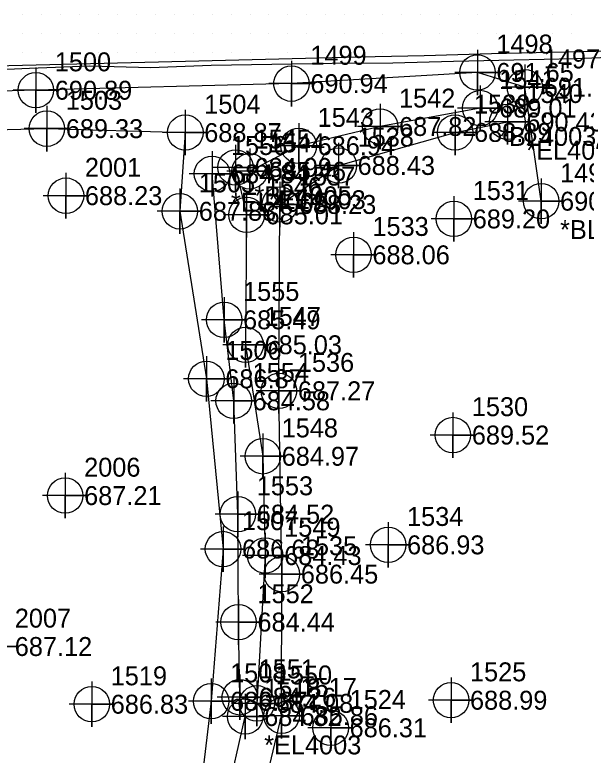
# Model space of a CAD drawing. Extents: x 1755643 to 1760494, y 736519 to 737621.
# Drawn here: x 1757975.2 to 1758050.6, y 736888.4 to 736986.2 of the extents above; entities that cross this region are included whole.
import ezdxf

# ---------------------------------------------------------------- set-up
doc = ezdxf.new("R2010")
doc.units = 0
for name, color, linetype in [('Exist Horizontal Alignment Curve and Spiral Data', 7, 'Continuous'), ('Exist Horizontal Alignment Direction Label', 7, 'Continuous'), ('Exist Roads EOT', 7, 'Continuous'), ('Old_Level_1', 7, 'Continuous'), ('Old_Level_10', 7, 'Continuous'), ('Old_Level_2', 7, 'Continuous'), ('Old_Level_3', 7, 'Continuous'), ('Prop Corridor Linear Feature', 7, 'Continuous'), ('Prop Dimension', 7, 'Continuous'), ('Prop EOT Dash', 7, 'Continuous'), ('Prop Horizontal Alignment Direction Label', 7, 'Continuous'), ('Prop Lane Lines', 7, 'Continuous'), ('Prop Paved Shoulder', 7, 'Continuous'), ('Scratch_Level_1', 7, 'Continuous'), ('Scratch_Level_2', 7, 'Continuous'), ('Scratch_Level_5', 7, 'Continuous'), ('Scratch_Level_9', 7, 'Continuous')]:
    doc.layers.add(name, color=color, linetype=linetype)

msp = doc.modelspace()

# ---------------------------------------------------------------- linework, layer by layer
at = {"layer": 'Exist Horizontal Alignment Curve and Spiral Data'}
for points in [[(1757981.934, 736965.342), (1757981.934, 736959.342), (1757981.934, 736962.342), (1757984.934, 736962.342), (1757978.934, 736962.342)], [(1758033.163, 736962.275), (1758033.163, 736956.275), (1758033.163, 736959.275), (1758036.163, 736959.275), (1758030.163, 736959.275)], [(1758019.913, 736957.526), (1758019.913, 736951.526), (1758019.913, 736954.526), (1758022.913, 736954.526), (1758016.913, 736954.526)], [(1758033.043, 736933.706), (1758033.043, 736927.706), (1758033.043, 736930.706), (1758036.043, 736930.706), (1758030.043, 736930.706)], [(1757981.831, 736925.705), (1757981.831, 736919.705), (1757981.831, 736922.705), (1757984.831, 736922.705), (1757978.831, 736922.705)], [(1758024.483, 736919.193), (1758024.483, 736913.193), (1758024.483, 736916.193), (1758027.483, 736916.193), (1758021.483, 736916.193)], [(1757972.671, 736905.755), (1757972.671, 736899.755), (1757972.671, 736902.755), (1757975.671, 736902.755), (1757969.671, 736902.755)], [(1758032.799, 736898.658), (1758032.799, 736892.658), (1758032.799, 736895.658), (1758035.799, 736895.658), (1758029.799, 736895.658)], [(1757985.344, 736898.13), (1757985.344, 736892.13), (1757985.344, 736895.13), (1757988.344, 736895.13), (1757982.344, 736895.13)], [(1758016.898, 736895.01), (1758016.898, 736889.01), (1758016.898, 736892.01), (1758019.898, 736892.01), (1758013.898, 736892.01)]]:
    msp.add_lwpolyline(points, dxfattribs=at)
for centre in [(1757981.934, 736962.342), (1758033.163, 736959.275), (1758019.913, 736954.526), (1758033.043, 736930.706), (1757981.831, 736922.705), (1758024.483, 736916.193), (1758032.799, 736895.658), (1757985.344, 736895.13), (1758016.898, 736892.01)]:
    msp.add_circle(centre, 2.344, dxfattribs=at)
at = {"layer": 'Old_Level_10'}
for points in [[(1758036.655, 736976.924), (1758036.655, 736970.924), (1758036.655, 736973.924), (1758039.655, 736973.924), (1758033.655, 736973.924)], [(1758023.425, 736974.488), (1758023.425, 736968.488), (1758023.425, 736971.488), (1758026.425, 736971.488), (1758020.425, 736971.488)], [(1758012.674, 736971.939), (1758012.674, 736965.939), (1758012.674, 736968.939), (1758015.674, 736968.939), (1758009.674, 736968.939)], [(1758006.2, 736968.565), (1758006.2, 736962.565), (1758006.2, 736965.565), (1758009.2, 736965.565), (1758003.2, 736965.565)], [(1758005.617, 736896.499), (1758005.617, 736890.499), (1758005.617, 736893.499), (1758008.617, 736893.499), (1758002.617, 736893.499)]]:
    msp.add_lwpolyline(points, dxfattribs=at)
for centre in [(1758036.655, 736973.924), (1758023.425, 736971.488), (1758012.674, 736968.939), (1758006.2, 736965.565), (1758005.617, 736893.499)]:
    msp.add_circle(centre, 2.344, dxfattribs=at)
at = {"layer": 'Prop Corridor Linear Feature'}
msp.add_lwpolyline([(1758061.811, 736980.821), (1758057.085, 736980.756), (1758049.092, 736980.415), (1758041.095, 736980.272), (1758035.133, 736980.136)], dxfattribs=at)
at = {"layer": 'Prop Dimension'}
for points in [[(1758036.655, 736973.924), (1758023.425, 736971.488), (1758012.674, 736968.939), (1758006.2, 736965.565)], [(1757999.898, 736844.317), (1758002.22, 736861.196), (1758003.101, 736882.388), (1758005.617, 736893.499)]]:
    msp.add_lwpolyline(points, dxfattribs=at)
at = {"layer": 'Prop Lane Lines'}
for points in [[(1758036.282, 736981.633), (1758036.282, 736975.633), (1758036.282, 736978.633), (1758039.282, 736978.633), (1758033.282, 736978.633)], [(1758011.711, 736980.151), (1758011.711, 736974.151), (1758011.711, 736977.151), (1758014.711, 736977.151), (1758008.711, 736977.151)], [(1757977.961, 736979.281), (1757977.961, 736973.281), (1757977.961, 736976.281), (1757980.961, 736976.281), (1757974.961, 736976.281)], [(1758042.552, 736979.669), (1758042.552, 736973.669), (1758042.552, 736976.669), (1758045.552, 736976.669), (1758039.552, 736976.669)], [(1758040.239, 736975.095), (1758040.239, 736969.095), (1758040.239, 736972.095), (1758043.239, 736972.095), (1758037.239, 736972.095)], [(1757979.412, 736974.203), (1757979.412, 736968.203), (1757979.412, 736971.203), (1757982.412, 736971.203), (1757976.412, 736971.203)], [(1757997.696, 736973.685), (1757997.696, 736967.685), (1757997.696, 736970.685), (1758000.696, 736970.685), (1757994.696, 736970.685)], [(1758033.331, 736973.702), (1758033.331, 736967.702), (1758033.331, 736970.702), (1758036.331, 736970.702), (1758030.331, 736970.702)], [(1758004.339, 736969.074), (1758004.339, 736963.074), (1758004.339, 736966.074), (1758007.339, 736966.074), (1758001.339, 736966.074)], [(1758017.952, 736969.336), (1758017.952, 736963.336), (1758017.952, 736966.336), (1758020.952, 736966.336), (1758014.952, 736966.336)], [(1758001.225, 736968.223), (1758001.225, 736962.223), (1758001.225, 736965.223), (1758004.225, 736965.223), (1757998.225, 736965.223)], [(1758010.197, 736964.184), (1758010.197, 736958.184), (1758010.197, 736961.184), (1758013.197, 736961.184), (1758007.197, 736961.184)], [(1758044.699, 736964.616), (1758044.699, 736958.616), (1758044.699, 736961.616), (1758047.699, 736961.616), (1758041.699, 736961.616)], [(1757996.979, 736963.28), (1757996.979, 736957.28), (1757996.979, 736960.28), (1757999.979, 736960.28), (1757993.979, 736960.28)], [(1758005.801, 736962.808), (1758005.801, 736956.808), (1758005.801, 736959.808), (1758008.801, 736959.808), (1758002.801, 736959.808)], [(1758002.824, 736948.936), (1758002.824, 736942.936), (1758002.824, 736945.936), (1758005.824, 736945.936), (1757999.824, 736945.936)], [(1758005.664, 736945.637), (1758005.664, 736939.637), (1758005.664, 736942.637), (1758008.664, 736942.637), (1758002.664, 736942.637)], [(1758000.479, 736941.144), (1758000.479, 736935.144), (1758000.479, 736938.144), (1758003.479, 736938.144), (1757997.479, 736938.144)], [(1758010.063, 736939.555), (1758010.063, 736933.555), (1758010.063, 736936.555), (1758013.063, 736936.555), (1758007.063, 736936.555)], [(1758004.088, 736938.229), (1758004.088, 736932.229), (1758004.088, 736935.229), (1758007.088, 736935.229), (1758001.088, 736935.229)], [(1758007.927, 736930.899), (1758007.927, 736924.899), (1758007.927, 736927.899), (1758010.927, 736927.899), (1758004.927, 736927.899)], [(1758004.639, 736923.246), (1758004.639, 736917.246), (1758004.639, 736920.246), (1758007.639, 736920.246), (1758001.639, 736920.246)], [(1758002.682, 736918.636), (1758002.682, 736912.636), (1758002.682, 736915.636), (1758005.682, 736915.636), (1757999.682, 736915.636)], [(1758008.253, 736917.774), (1758008.253, 736911.774), (1758008.253, 736914.774), (1758011.253, 736914.774), (1758005.253, 736914.774)], [(1758010.458, 736915.323), (1758010.458, 736909.323), (1758010.458, 736912.323), (1758013.458, 736912.323), (1758007.458, 736912.323)], [(1758004.728, 736908.983), (1758004.728, 736902.983), (1758004.728, 736905.983), (1758007.728, 736905.983), (1758001.728, 736905.983)], [(1758004.886, 736899.047), (1758004.886, 736893.047), (1758004.886, 736896.047), (1758007.886, 736896.047), (1758001.886, 736896.047)], [(1758001.112, 736898.521), (1758001.112, 736892.521), (1758001.112, 736895.521), (1758004.112, 736895.521), (1757998.112, 736895.521)], [(1758007.153, 736898.243), (1758007.153, 736892.243), (1758007.153, 736895.243), (1758010.153, 736895.243), (1758004.153, 736895.243)], [(1758010.422, 736896.611), (1758010.422, 736890.611), (1758010.422, 736893.611), (1758013.422, 736893.611), (1758007.422, 736893.611)]]:
    msp.add_lwpolyline(points, dxfattribs=at)
for centre in [(1758036.282, 736978.633), (1758011.711, 736977.151), (1758042.552, 736976.669), (1757977.961, 736976.281), (1758040.239, 736972.095), (1757979.412, 736971.203), (1757997.696, 736970.685), (1758033.331, 736970.702), (1758004.339, 736966.074), (1758017.952, 736966.336), (1758001.225, 736965.223), (1758010.197, 736961.184), (1758044.699, 736961.616), (1757996.979, 736960.28), (1758005.801, 736959.808), (1758002.824, 736945.936), (1758005.664, 736942.637), (1758000.479, 736938.144), (1758010.063, 736936.555), (1758004.088, 736935.229), (1758007.927, 736927.899), (1758004.639, 736920.246), (1758002.682, 736915.636), (1758008.253, 736914.774), (1758010.458, 736912.323), (1758004.728, 736905.983), (1758001.112, 736895.521), (1758004.886, 736896.047), (1758007.153, 736895.243), (1758010.422, 736893.611)]:
    msp.add_circle(centre, 2.344, dxfattribs=at)
at = {"layer": 'Scratch_Level_1'}
msp.add_lwpolyline([(1758035.133, 736980.136), (1758033.101, 736980.089), (1758025.106, 736979.841), (1758017.105, 736979.803), (1758009.107, 736979.667), (1758001.107, 736979.558), (1757993.114, 736979.258), (1757985.107, 736979.44), (1757977.112, 736979.133), (1757969.119, 736978.796), (1757961.126, 736978.427), (1757953.119, 736978.601), (1757945.126, 736978.242), (1757937.132, 736977.975), (1757929.137, 736977.68), (1757921.134, 736977.682), (1757913.141, 736977.275), (1757909.254, 736977.133)], dxfattribs=at)
at = {"layer": 'Scratch_Level_2'}
for p, q in [((1757976.25, 736986.25), (1757976.25, 736986.25)), ((1757978.75, 736986.25), (1757978.75, 736986.25)), ((1757981.25, 736986.25), (1757981.25, 736986.25)), ((1757983.75, 736986.25), (1757983.75, 736986.25)), ((1757986.25, 736986.25), (1757986.25, 736986.25)), ((1757988.75, 736986.25), (1757988.75, 736986.25)), ((1757991.25, 736986.25), (1757991.25, 736986.25)), ((1757993.75, 736986.25), (1757993.75, 736986.25)), ((1757996.25, 736986.25), (1757996.25, 736986.25)), ((1757998.75, 736986.25), (1757998.75, 736986.25)), ((1758001.25, 736986.25), (1758001.25, 736986.25)), ((1758003.75, 736986.25), (1758003.75, 736986.25)), ((1758006.25, 736986.25), (1758006.25, 736986.25)), ((1758008.75, 736986.25), (1758008.75, 736986.25)), ((1758011.25, 736986.25), (1758011.25, 736986.25)), ((1758013.75, 736986.25), (1758013.75, 736986.25)), ((1758016.25, 736986.25), (1758016.25, 736986.25)), ((1758018.75, 736986.25), (1758018.75, 736986.25)), ((1758021.25, 736986.25), (1758021.25, 736986.25)), ((1758023.75, 736986.25), (1758023.75, 736986.25)), ((1758026.25, 736986.25), (1758026.25, 736986.25)), ((1758028.75, 736986.25), (1758028.75, 736986.25)), ((1758031.25, 736986.25), (1758031.25, 736986.25)), ((1758033.75, 736986.25), (1758033.75, 736986.25)), ((1758036.25, 736986.25), (1758036.25, 736986.25)), ((1758038.75, 736986.25), (1758038.75, 736986.25)), ((1758041.25, 736986.25), (1758041.25, 736986.25)), ((1758043.75, 736986.25), (1758043.75, 736986.25)), ((1758046.25, 736986.25), (1758046.25, 736986.25)), ((1758048.75, 736986.25), (1758048.75, 736986.25)), ((1757976.25, 736983.75), (1757976.25, 736983.75)), ((1757978.75, 736983.75), (1757978.75, 736983.75)), ((1757981.25, 736983.75), (1757981.25, 736983.75)), ((1757983.75, 736983.75), (1757983.75, 736983.75)), ((1757986.25, 736983.75), (1757986.25, 736983.75)), ((1757988.75, 736983.75), (1757988.75, 736983.75)), ((1757991.25, 736983.75), (1757991.25, 736983.75)), ((1757993.75, 736983.75), (1757993.75, 736983.75)), ((1757996.25, 736983.75), (1757996.25, 736983.75)), ((1757998.75, 736983.75), (1757998.75, 736983.75)), ((1758001.25, 736983.75), (1758001.25, 736983.75)), ((1758003.75, 736983.75), (1758003.75, 736983.75)), ((1758006.25, 736983.75), (1758006.25, 736983.75)), ((1758008.75, 736983.75), (1758008.75, 736983.75)), ((1758011.25, 736983.75), (1758011.25, 736983.75)), ((1758013.75, 736983.75), (1758013.75, 736983.75)), ((1758016.25, 736983.75), (1758016.25, 736983.75)), ((1758018.75, 736983.75), (1758018.75, 736983.75)), ((1758021.25, 736983.75), (1758021.25, 736983.75)), ((1758023.75, 736983.75), (1758023.75, 736983.75)), ((1758026.25, 736983.75), (1758026.25, 736983.75)), ((1758028.75, 736983.75), (1758028.75, 736983.75)), ((1758031.25, 736983.75), (1758031.25, 736983.75)), ((1758033.75, 736983.75), (1758033.75, 736983.75)), ((1758036.25, 736983.75), (1758036.25, 736983.75)), ((1758038.75, 736983.75), (1758038.75, 736983.75)), ((1758041.25, 736983.75), (1758041.25, 736983.75)), ((1758043.75, 736983.75), (1758043.75, 736983.75)), ((1758046.25, 736983.75), (1758046.25, 736983.75)), ((1758048.75, 736983.75), (1758048.75, 736983.75)), ((1757976.25, 736981.25), (1757976.25, 736981.25)), ((1757978.75, 736981.25), (1757978.75, 736981.25)), ((1757981.25, 736981.25), (1757981.25, 736981.25)), ((1757983.75, 736981.25), (1757983.75, 736981.25)), ((1757986.25, 736981.25), (1757986.25, 736981.25)), ((1757988.75, 736981.25), (1757988.75, 736981.25)), ((1757991.25, 736981.25), (1757991.25, 736981.25)), ((1757993.75, 736981.25), (1757993.75, 736981.25)), ((1757996.25, 736981.25), (1757996.25, 736981.25)), ((1757998.75, 736981.25), (1757998.75, 736981.25)), ((1758001.25, 736981.25), (1758001.25, 736981.25)), ((1758003.75, 736981.25), (1758003.75, 736981.25)), ((1758006.25, 736981.25), (1758006.25, 736981.25)), ((1758008.75, 736981.25), (1758008.75, 736981.25)), ((1758011.25, 736981.25), (1758011.25, 736981.25)), ((1758013.75, 736981.25), (1758013.75, 736981.25)), ((1758016.25, 736981.25), (1758016.25, 736981.25)), ((1758018.75, 736981.25), (1758018.75, 736981.25)), ((1758021.25, 736981.25), (1758021.25, 736981.25)), ((1758023.75, 736981.25), (1758023.75, 736981.25))]:
    msp.add_line(p, q, dxfattribs=at)
at = {"layer": 'Scratch_Level_5'}
msp.add_lwpolyline([(1758065.758, 736981.725), (1758038.129, 736981.07), (1758029.226, 736980.816), (1758020.635, 736980.632), (1757997.713, 736980.082), (1757970.759, 736979.407), (1757939.721, 736978.58), (1757928.953, 736978.26), (1757915.672, 736977.877), (1757898.955, 736977.479), (1757878.164, 736976.8), (1757865.099, 736976.448)], dxfattribs=at)
at = {"layer": 'Scratch_Level_9'}
for points in [[(1758044.699, 736961.616), (1758042.552, 736976.669), (1758036.282, 736978.633), (1758011.711, 736977.151), (1757977.961, 736976.281), (1757948.416, 736975.444)], [(1758003.767, 736845.328), (1758006.907, 736860.939), (1758007.525, 736881.578), (1758010.422, 736893.611), (1758010.458, 736912.323), (1758010.063, 736936.555), (1758010.197, 736961.184), (1758017.952, 736966.336), (1758033.331, 736970.702), (1758040.239, 736972.095)], [(1757948.283, 736970.452), (1757979.412, 736971.203), (1757997.696, 736970.685), (1757996.979, 736960.28), (1758000.479, 736938.144), (1758002.682, 736915.636), (1758001.112, 736895.521), (1757997.986, 736869.316), (1757996.697, 736844.115)], [(1758004.339, 736966.074), (1758005.801, 736959.808), (1758005.664, 736942.637), (1758007.927, 736927.899), (1758008.253, 736914.774), (1758007.153, 736895.243), (1758004.886, 736896.047), (1758004.728, 736905.983), (1758004.639, 736920.246), (1758004.088, 736935.229), (1758002.824, 736945.936), (1758001.225, 736965.223)]]:
    msp.add_lwpolyline(points, dxfattribs=at)

# ---------------------------------------------------------------- texts
at = {"layer": 'Exist Horizontal Alignment Direction Label'}
for s, p in [('*EL4005', (1758042.739, 736967.095)), ('*BL4005', (1758006.839, 736961.074)), ('*EL4005', (1758003.725, 736960.223)), ('*BL4005', (1758047.199, 736956.616))]:
    msp.add_text(s, height=2.5, dxfattribs=at).set_placement(p)
at = {"layer": 'Exist Roads EOT'}
for s, p in [('2001', (1757984.434, 736964.842)), ('1531', (1758035.663, 736961.775)), ('1533', (1758022.413, 736957.026)), ('1530', (1758035.543, 736933.206)), ('2006', (1757984.331, 736925.205)), ('1534', (1758026.983, 736918.693)), ('2007', (1757975.171, 736905.255)), ('1525', (1758035.299, 736898.158)), ('1519', (1757987.844, 736897.63)), ('1524', (1758019.398, 736894.51))]:
    msp.add_text(s, height=2.5, dxfattribs=at).set_placement(p)
at = {"layer": 'Old_Level_1'}
for s, p in [('1541', (1758039.155, 736976.424)), ('1542', (1758025.925, 736973.988)), ('1543', (1758015.174, 736971.439)), ('1544', (1758008.7, 736968.065)), ('1518', (1758008.117, 736895.999))]:
    msp.add_text(s, height=2.5, dxfattribs=at).set_placement(p)
at = {"layer": 'Old_Level_2'}
for s, p in [('689.01', (1758039.155, 736972.674)), ('687.82', (1758025.925, 736970.238)), ('686.94', (1758015.174, 736967.689)), ('685.46', (1758008.7, 736964.315)), ('684.32', (1758008.117, 736892.249))]:
    msp.add_text(s, height=2.5, dxfattribs=at).set_placement(p)
at = {"layer": 'Old_Level_3'}
for s, p in [('691.65', (1758038.782, 736977.383)), ('690.94', (1758014.211, 736975.901)), ('691.94', (1758045.052, 736975.419)), ('690.89', (1757980.461, 736975.031)), ('690.43', (1758042.739, 736970.845)), ('689.33', (1757981.912, 736969.953)), ('688.89', (1758035.831, 736969.452)), ('688.87', (1758000.196, 736969.435)), ('684.99', (1758006.839, 736964.824)), ('688.43', (1758020.452, 736965.086)), ('684.84', (1758003.725, 736963.973)), ('688.23', (1758012.697, 736959.934)), ('690.84', (1758047.199, 736960.366)), ('687.88', (1757999.479, 736959.03)), ('685.01', (1758008.301, 736958.558)), ('685.49', (1758005.324, 736944.686)), ('685.03', (1758008.164, 736941.387)), ('686.87', (1758002.979, 736936.894)), ('687.27', (1758012.563, 736935.305)), ('684.58', (1758006.588, 736933.979)), ('684.97', (1758010.427, 736926.649)), ('684.52', (1758007.139, 736918.996)), ('686.68', (1758005.182, 736914.386)), ('684.43', (1758010.753, 736913.524)), ('686.45', (1758012.958, 736911.073)), ('684.44', (1758007.228, 736904.733)), ('686.37', (1758003.612, 736894.271)), ('684.26', (1758007.386, 736894.797)), ('684.08', (1758009.653, 736893.993)), ('685.86', (1758012.922, 736892.361))]:
    msp.add_text(s, height=2.5, dxfattribs=at).set_placement(p)
at = {"layer": 'Prop EOT Dash'}
for s, p in [('1498', (1758038.782, 736981.133)), ('1499', (1758014.211, 736979.651)), ('1500', (1757980.461, 736978.781)), ('1497', (1758045.052, 736979.169)), ('1540', (1758042.739, 736974.595)), ('1503', (1757981.912, 736973.703)), ('1504', (1758000.196, 736973.185)), ('1539', (1758035.831, 736973.202)), ('1545', (1758006.839, 736968.574)), ('1538', (1758020.452, 736968.836)), ('1556', (1758003.725, 736967.723)), ('1537', (1758012.697, 736963.684)), ('1496', (1758047.199, 736964.116)), ('1505', (1757999.479, 736962.78)), ('1546', (1758008.301, 736962.308)), ('1555', (1758005.324, 736948.436)), ('1547', (1758008.164, 736945.137)), ('1506', (1758002.979, 736940.644)), ('1536', (1758012.563, 736939.055)), ('1554', (1758006.588, 736937.729)), ('1548', (1758010.427, 736930.399)), ('1553', (1758007.139, 736922.746)), ('1507', (1758005.182, 736918.136)), ('1549', (1758010.753, 736917.274)), ('1535', (1758012.958, 736914.823)), ('1552', (1758007.228, 736908.483)), ('1508', (1758003.612, 736898.021)), ('1551', (1758007.386, 736898.547)), ('1550', (1758009.653, 736897.743)), ('1517', (1758012.922, 736896.111))]:
    msp.add_text(s, height=2.5, dxfattribs=at).set_placement(p)
at = {"layer": 'Prop Horizontal Alignment Direction Label'}
for s, p in [('*BL4003', (1758039.155, 736968.924)), ('*EL4003', (1758008.7, 736960.565)), ('*EL4003', (1758008.117, 736888.499))]:
    msp.add_text(s, height=2.5, dxfattribs=at).set_placement(p)
at = {"layer": 'Prop Paved Shoulder'}
for s, p in [('688.23', (1757984.434, 736961.092)), ('689.20', (1758035.663, 736958.025)), ('688.06', (1758022.413, 736953.276)), ('689.52', (1758035.543, 736929.456)), ('687.21', (1757984.331, 736921.455)), ('686.93', (1758026.983, 736914.943)), ('687.12', (1757975.171, 736901.505)), ('688.99', (1758035.299, 736894.408)), ('686.83', (1757987.844, 736893.88)), ('686.31', (1758019.398, 736890.76))]:
    msp.add_text(s, height=2.5, dxfattribs=at).set_placement(p)

doc.saveas('drawing.dxf')
